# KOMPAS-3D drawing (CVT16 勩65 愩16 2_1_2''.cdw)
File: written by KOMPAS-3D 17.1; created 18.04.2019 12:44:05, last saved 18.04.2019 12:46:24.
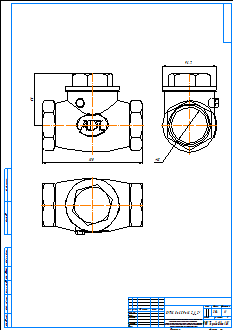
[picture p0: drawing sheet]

Sheet 1: A2, portrait

Title block, sheet 1: name: CVT16 Ду65 Ру16 2_1_2''; material: Внимание! Данный продукт является объектом авторского права ООО «Торговый Дом АДЛ». / Запрещается изменение, копирование, распространение / (в том числе путем копирования на другие сайты и ресурсы в Интернете) / или любое иное использование информации и объектов без предварительного / согласия правообладателя (ООО «Торговый Дом АДЛ»).; mass: 3,04; sheets: 1; organisation: ООО "Торговый дом АДЛ"; sheet format: A2

Views: Спереди 1, Проекционный вид 2, Проекционный вид 3
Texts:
  user
Dimensions and other numbers on the sheet: 180; 93; 96,7; 65; 1:1; 1; 3,04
